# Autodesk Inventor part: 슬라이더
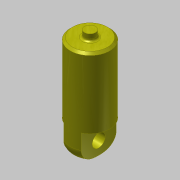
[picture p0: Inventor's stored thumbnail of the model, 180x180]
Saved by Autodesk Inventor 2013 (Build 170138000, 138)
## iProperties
Created: 2016-08
Part Number: 슬라이더
Material: 강철, 탄소
Document SubType Name: Modeling
Designer: mduedu
Density: 7.87 g/cm^3
Mass: 75.783 g
Surface Area: 29.7428 cm^2
Volume: 9.62936 cm^3
Author: mduedu
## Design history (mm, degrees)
sketch "스케치1"
  geometry: C1 r 9 at (0, 0); 1 further point
  constraints: 1 centre point, 1 coincident
  dimensions: "d0" = 18 diameter of C1
extrude "돌출1" new body sketch "스케치1" distance "d1" = 45; taper "d2" = 0 deg
fillet "모깎기1" dims "d21" = 6
sketch "스케치6"
  geometry: L1 (9, 6)-(9, 45) reference; L2 (-9, 6)-(-9, 45) reference; L3 (9, 45)-(-9, 45) reference; L4 (0, 45)-(0, 0); L5 (9, 13)-(4, 13); L6 (4, 13)-(4, 0); L7 (4, 0)-(9, 0); L8 (9, 0)-(9, 13); L9 (-9, 13)-(-4, 13); L10 (-4, 13)-(-4, 0); L11 (-4, 0)-(-9, 0); L12 (-9, 0)-(-9, 13)
  constraints: 18 end point, 4 symmetric about line, 2 parallel, 2 perpendicular, 1 horizontal, 1 horizontal alignment, 1 midpoint, 1 point on line
  dimensions: "d22" = 13 distance of L7.end L5.start; "d24" = 4 distance between parallel lines of L6 L4
extrude "돌출5" cut sketch "스케치6" stored distance "d25" = 8; taper "d26" = 0 deg
sketch "스케치8"
  geometry: C1 r 3 at (6, 0); 1 further point
  constraints: 1 centre point, 1 horizontal alignment
  dimensions: "d27" = 6 diameter of C1; "d28" = 6 distance of point (0, 0) C1.centre
extrude "돌출6" cut sketch "스케치8" stored distance "d29" = 8; taper "d30" = 0 deg
chamfer "모따기2" distance "d43" = 1; stored, may be unused: second distance "d44" = 2, angle "d45" = 30 deg
sketch "스케치9"
  geometry: C1 r 2.5 at (0, 0); 1 further point
  constraints: 1 centre point, 1 coincident
  dimensions: "d47" = 5 diameter of C1
extrude "돌출7" join sketch "스케치9" distance "d48" = 3; taper "d49" = 0 deg
fillet "모깎기2" dims "d50" = 1
node "솔리드1"
